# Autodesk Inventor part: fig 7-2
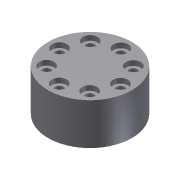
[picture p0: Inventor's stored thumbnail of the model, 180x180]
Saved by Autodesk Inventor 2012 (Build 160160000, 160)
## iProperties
Created: 2004-05
Part Number: fig 7-2
Document SubType Name: Modeling
Designer: CADCIM Technologies
Manufacturer: Standard
Standards Organization: Custom
Density: 1 g/cm^3
Material: Default
Author: CADCIM Technologies
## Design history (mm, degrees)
sketch "Sketch1"
  geometry: C1 r 17.175 at (0, 0)
  constraints: 1 centre point
extrude "Extrusion1" new body sketch "Sketch1" distance "d0" = 17; taper "d1" = 0 deg
sketch "Sketch2"
  geometry: 1 further point
hole "Hole1" sketch "Sketch2" at (12.571, -0.074) diameter "d2" = 3.5; stored, may be unused: countersink angle "d6" = 90 deg, drill point angle "d8" = 118 deg; dims "d3" = 6, "d4" = 6, "d5" = 2, "d7" = 8
pattern_circular "Circular Pattern1" dims angle "d11" = 360 deg
body "Solid1"
